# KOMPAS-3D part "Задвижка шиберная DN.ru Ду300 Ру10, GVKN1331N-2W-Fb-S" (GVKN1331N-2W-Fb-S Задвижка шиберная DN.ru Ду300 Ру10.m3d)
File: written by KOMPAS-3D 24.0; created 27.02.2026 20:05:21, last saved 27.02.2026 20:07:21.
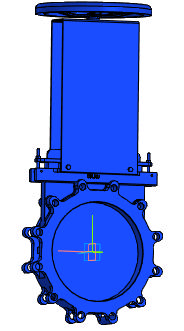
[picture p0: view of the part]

Document properties: Автор: R2D2; Полное имя файла: GVKN1331N-2W-Fb-S Задвижка шиберная DN.ru Ду300 Ру10.cdw

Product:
- Part/product: Задвижка шиберная DN.ru Ду300 Ру10  | designation GVKN1331N-2W-Fb-S
    Масса: 49
    Раздел спецификации: Прочие изделия
    Форматы листов документа: A2
    Примечание: D040-07884
    additional columns: D040-07884

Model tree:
1. Операция без истории:1

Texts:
  GVKN1331N-2W-Fb-S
